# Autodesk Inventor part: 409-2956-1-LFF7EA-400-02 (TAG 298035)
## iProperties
Created: 2010-06
Part Number: 409-2956-1-LFF7EA-400-02 (TAG 298035)
Material: 1/16"Thk PLASTIC
Document SubType Name: Modeling
Designer: S. Boerckel
Engineer: Steve Boerckel
Mass: 230.369 g
Surface Area: 3121.56 cm^2
Volume: 245.074 cm^3
Density: 0.94 g/cm^3
Description: TAG
SMR: =<Material>
Length: 20.000 in
Wide: 12.000 in
Thickness: 0.063 in
Author: S. Boerckel
Revision Number: 0
Subject: DEMIN WATER FORWARDING PUMP SKID-7EA
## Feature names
1. Extrusion1
2. Hole1
